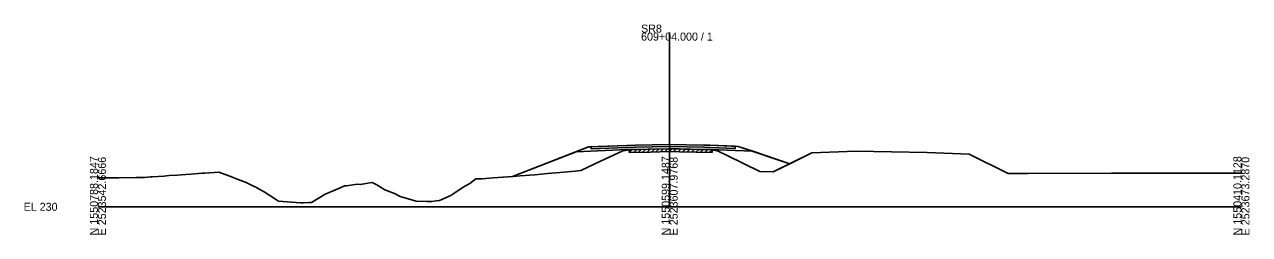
# Model space of a CAD drawing. Extents: x -26 to 2803, y -10 to 19537.
# Drawn here: x -25.7 to 402.8, y 14990.3 to 15063.8 of the extents above; entities that cross this region are included whole.
import ezdxf

# ---------------------------------------------------------------- set-up
doc = ezdxf.new("R2010")
doc.units = 0
for name, color, linetype in [('1', 7, 'Continuous'), ('Draft_XS_Grid', 7, 'Continuous'), ('Draft_XS_Text', 7, 'Continuous'), ('DTM_P_SUBGRADE_1', 7, 'Continuous'), ('DTM_X_GROUND', 7, 'Continuous'), ('SLOPE_STAKES_FILL', 7, 'Continuous'), ('XS_P_ASPHALT', 7, 'Continuous'), ('XS_P_SHOULDER', 7, 'Continuous')]:
    doc.layers.add(name, color=color, linetype=linetype)

msp = doc.modelspace()

# ---------------------------------------------------------------- linework, layer by layer
at = {"layer": '1'}
for p, q in [((200, 15000), (200, 15060.94)), ((0, 15000), (200, 15000)), ((200, 15000), (400, 15000))]:
    msp.add_line(p, q, dxfattribs=at)
at = {"layer": 'Draft_XS_Grid'}
for p, q in [((190.53, 15019.08), (191.59, 15020.1)), ((192.08, 15019.11), (193.14, 15020.14)), ((193.63, 15019.15), (194.69, 15020.18)), ((195.19, 15019.19), (196.25, 15020.21)), ((196.74, 15019.22), (197.8, 15020.25)), ((198.29, 15019.26), (199.35, 15020.29)), ((199.84, 15019.3), (200.88, 15020.3)), ((201.39, 15019.29), (202.4, 15020.26)), ((202.95, 15019.25), (203.95, 15020.22)), ((204.5, 15019.21), (205.51, 15020.18)), ((206.05, 15019.17), (207.06, 15020.14)), ((207.6, 15019.13), (208.61, 15020.1)), ((185.87, 15018.97), (186.93, 15019.99)), ((185.87, 15018.97), (185.87, 15019.97)), ((185.87, 15018.97), (193.2, 15019.14)), ((187.43, 15019), (188.49, 15020.03)), ((188.98, 15019.04), (190.04, 15020.07)), ((193.2, 15019.14), (200, 15019.3)), ((200, 15019.3), (200.46, 15019.31)), ((200.46, 15019.31), (203.44, 15019.23)), ((203.44, 15019.23), (214.85, 15018.94)), ((209.16, 15019.09), (210.16, 15020.06)), ((210.71, 15019.05), (211.72, 15020.02)), ((212.26, 15019.01), (213.27, 15019.98)), ((213.81, 15018.97), (214.82, 15019.94)), ((214.85, 15019.94), (214.85, 15018.94))]:
    msp.add_line(p, q, dxfattribs=at)
at = {"layer": 'Draft_XS_Text'}
for p, q in [((236.17, 15012.18), (249.73, 15018.83)), ((249.73, 15018.83), (265.22, 15019.43)), ((265.22, 15019.43), (277.65, 15019.2)), ((277.65, 15019.2), (290.07, 15018.98)), ((290.07, 15018.98), (304.8, 15018.41)), ((304.8, 15018.41), (318.42, 15011.6))]:
    msp.add_line(p, q, dxfattribs=at)
for points in [[(0, 15010.09), (1.34, 15010.11), (6.37, 15010.16), (7.29, 15010.17), (13.38, 15010.23), (16.31, 15010.26), (18.41, 15010.43), (18.99, 15010.47), (23.04, 15010.77), (24.87, 15010.91), (27.76, 15011.12), (30.71, 15011.33), (32.53, 15011.47), (36.5, 15011.75), (37.37, 15011.82), (42.31, 15012.17), (47.08, 15010.39), (48.17, 15009.9), (51.85, 15008.47), (54.14, 15007.38), (55.41, 15006.7), (56.43, 15006.22), (58.19, 15005.29), (62.49, 15002.48), (63.15, 15002.02), (67.68, 15001.62), (71.02, 15001.38), (71.85, 15001.42), (73.95, 15001.52), (74.75, 15001.56), (79.52, 15004.46), (82.29, 15005.59), (84.76, 15006.69), (86.26, 15007.37), (86.92, 15007.32), (90.7, 15007.88), (91.75, 15007.78), (95.81, 15008.47), (96.4, 15008.22), (97.61, 15007.72), (100.33, 15005.92), (103.76, 15004.67), (105.74, 15003.65), (111.32, 15001.93), (115.03, 15001.86), (116.81, 15001.9), (118.28, 15002.05), (119.46, 15002.16), (123.41, 15003.95), (124.13, 15004.43), (127.79, 15006.86), (130.1, 15008.16), (132.15, 15009.75), (134.05, 15009.82), (134.41, 15009.82), (138.29, 15010.16), (145.21, 15010.62), (147.74, 15010.84), (152.89, 15011.2), (157.3, 15011.61), (160.35, 15011.84), (166.99, 15012.51), (167.82, 15012.57), (168.89, 15012.71), (175.62, 15015.84), (183.59, 15019.56), (184.53, 15019.73), (185.87, 15019.97), (193.2, 15020.14), (200, 15020.3), (200.46, 15020.31), (203.44, 15020.23), (214.85, 15019.94), (216.51, 15019.58), (216.98, 15019.47), (220.33, 15017.86), (231.55, 15012.4), (236.17, 15012.18)], [(318.42, 15011.6), (325.2, 15011.65), (354.53, 15011.72), (400, 15011.78)]]:
    msp.add_lwpolyline(points, dxfattribs=at)
at = {"layer": 'DTM_P_SUBGRADE_1'}
for p, q in [((200, 15020.3), (185.07, 15020)), ((200, 15020.3), (212, 15020.06)), ((185.07, 15020), (167.27, 15019.28)), ((212, 15020.06), (214, 15020.02)), ((214, 15020.02), (229.11, 15019.41))]:
    msp.add_line(p, q, dxfattribs=at)
at = {"layer": 'DTM_X_GROUND'}
for p, q in [((171.55, 15020.96), (145.04, 15010.61)), ((185.07, 15021.5), (171.55, 15020.96)), ((188, 15021.56), (185.07, 15021.5)), ((188, 15021.56), (200, 15021.8)), ((200, 15021.8), (212, 15021.56)), ((212, 15021.56), (214, 15021.52)), ((214, 15021.52), (224, 15021.12)), ((224, 15021.12), (242.09, 15015.08))]:
    msp.add_line(p, q, dxfattribs=at)
at = {"layer": 'SLOPE_STAKES_FILL'}
for p, q in [((145.04, 15010.61), (171.55, 15020.96)), ((171.55, 15020.96), (185.07, 15021.5)), ((185.07, 15021.5), (188, 15021.56)), ((188, 15021.56), (200, 15021.8)), ((200, 15021.8), (212, 15021.56)), ((212, 15021.56), (214, 15021.52)), ((214, 15021.52), (224, 15021.12)), ((224, 15021.12), (242.09, 15015.08)), ((242.09, 15015.08), (249.73, 15018.83)), ((249.73, 15018.83), (265.22, 15019.43)), ((265.22, 15019.43), (277.65, 15019.2)), ((277.65, 15019.2), (290.07, 15018.98)), ((290.07, 15018.98), (304.8, 15018.41)), ((304.8, 15018.41), (318.42, 15011.6))]:
    msp.add_line(p, q, dxfattribs=at)
for points in [[(0, 15010.09), (1.34, 15010.11), (6.37, 15010.16), (7.29, 15010.17), (13.38, 15010.23), (16.31, 15010.26), (18.41, 15010.43), (18.99, 15010.47), (23.04, 15010.77), (24.87, 15010.91), (27.76, 15011.12), (30.71, 15011.33), (32.53, 15011.47), (36.5, 15011.75), (37.37, 15011.82), (42.31, 15012.17), (47.08, 15010.39), (48.17, 15009.9), (51.85, 15008.47), (54.14, 15007.38), (55.41, 15006.7), (56.43, 15006.22), (58.19, 15005.29), (62.49, 15002.48), (63.15, 15002.02), (67.68, 15001.62), (71.02, 15001.38), (71.85, 15001.42), (73.95, 15001.52), (74.75, 15001.56), (79.52, 15004.46), (82.29, 15005.59), (84.76, 15006.69), (86.26, 15007.37), (86.92, 15007.32), (90.7, 15007.88), (91.75, 15007.78), (95.81, 15008.47), (96.4, 15008.22), (97.61, 15007.72), (100.33, 15005.92), (103.76, 15004.67), (105.74, 15003.65), (111.32, 15001.93), (115.03, 15001.86), (116.81, 15001.9), (118.28, 15002.05), (119.46, 15002.16), (123.41, 15003.95), (124.13, 15004.43), (127.79, 15006.86), (130.1, 15008.16), (132.15, 15009.75), (134.05, 15009.82), (134.41, 15009.82), (138.29, 15010.16), (145.04, 15010.61)], [(318.42, 15011.6), (325.2, 15011.65), (354.53, 15011.72), (400, 15011.78)]]:
    msp.add_lwpolyline(points, dxfattribs=at)
at = {"layer": 'XS_P_ASPHALT'}
for p, q in [((172.54, 15020.25), (172.54, 15021)), ((185.07, 15020.75), (172.54, 15020.25)), ((188, 15020.81), (185.07, 15020.75)), ((188, 15020.81), (200, 15021.05)), ((200, 15021.05), (212, 15020.81)), ((212, 15020.81), (214, 15020.77)), ((214, 15020.77), (222.97, 15020.41)), ((222.97, 15020.41), (222.97, 15021.16))]:
    msp.add_line(p, q, dxfattribs=at)
at = {"layer": 'XS_P_SHOULDER'}
for points in [[(145.21, 15010.62), (147.74, 15010.84), (152.89, 15011.2), (157.3, 15011.61), (160.35, 15011.84), (166.99, 15012.51), (167.82, 15012.57), (168.89, 15012.71), (175.62, 15015.84), (183.59, 15019.56), (184.53, 15019.73), (185.87, 15019.97), (193.2, 15020.14), (200, 15020.3), (185.07, 15020), (167.27, 15019.28), (145.04, 15010.61)], [(200, 15021.05), (212, 15020.81), (214, 15020.77), (222.97, 15020.41), (222.97, 15021.16), (224, 15021.12), (229.11, 15019.41), (214, 15020.02), (212, 15020.06), (204.76, 15020.2), (203.44, 15020.23), (200.46, 15020.31), (200, 15020.3), (185.07, 15020), (167.27, 15019.28), (171.55, 15020.96), (172.54, 15021), (172.54, 15020.25), (185.07, 15020.75), (188, 15020.81)], [(200, 15021.05), (212, 15020.81), (214, 15020.77), (222.97, 15020.41), (222.97, 15021.16), (214, 15021.52), (212, 15021.56), (200, 15021.8), (188, 15021.56), (185.07, 15021.5), (172.54, 15021), (172.54, 15020.25), (185.07, 15020.75), (188, 15020.81)], [(203.44, 15020.23), (204.76, 15020.2), (200, 15020.3), (200.46, 15020.31)], [(214.85, 15019.94), (216.51, 15019.58), (216.98, 15019.47), (220.33, 15017.86), (231.55, 15012.4), (236.17, 15012.18), (242.09, 15015.08), (229.11, 15019.41), (214, 15020.02), (212, 15020.06), (204.76, 15020.2)]]:
    msp.add_lwpolyline(points, close=True, dxfattribs=at)

# ---------------------------------------------------------------- texts
at = {"layer": '1'}
for s, p in [('SR8', (190, 15060.94)), ('609+04.000 / 1', (190, 15058.14)), ('EL 230', (-26, 14998.6))]:
    msp.add_text(s, height=2.8, dxfattribs=at).set_placement(p)
for s, p in [('N 1550788.1847', (0, 14990)), ('E 2523542.6666', (2.8, 14990)), ('N 1550599.1487', (200, 14990)), ('E 2523607.9768', (202.8, 14990)), ('N 1550410.1128', (400, 14990)), ('E 2523673.2870', (402.8, 14990))]:
    msp.add_text(s, height=2.8, rotation=90, dxfattribs=at).set_placement(p)

doc.saveas('drawing.dxf')
